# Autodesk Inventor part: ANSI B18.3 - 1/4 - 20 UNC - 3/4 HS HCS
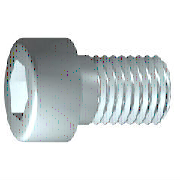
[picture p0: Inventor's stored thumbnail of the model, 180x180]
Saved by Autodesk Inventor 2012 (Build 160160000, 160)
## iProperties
IsCustomPart: 0
Created: 2011-02
Part Number: ANSI B18.3 - 1/4 - 20 UNC - 3/4 HS HCS
Material: Steel, Mild
Description: Hexagon Socket Head Cap Screw
Document SubType Name: Modeling
Standard: ANSI B18.3
Designer: Owner
Standard Revision: 2003
Standards Organization: ANSI
Language: en-US
Size Designation: 1/4 - 20 UNC - 3/4
Categories: <MemberInstance><Categories><Category DisplayName="Fasteners" InternalName="e4da775c-781d-43d5-af7c-5136215cf5a6" Mnemonic="FSTN"><Category DisplayName="Bolts"
Density: 7.86 g/cm^3
Mass: 7.66854 g
Surface Area: 7.48934 cm^2
Volume: 0.975641 cm^3
Author: Owner
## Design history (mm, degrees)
body "Solid1"
workplane "Work Plane1"
fillet "Fillet2" dims "d30" = 0.1778 (= R)
revolve "Body" stored, may be unused: angle "d10" = 90 deg
sketch "Sketch2"
  geometry: L1 (0, -6.668)-(0, 6.668) reference; L2 (-6.668, 0)-(6.668, 0) reference; L3 (2.757, 0)-(1.378, -2.388); L4 (1.378, -2.388)-(-1.378, -2.388); L5 (-1.378, -2.388)-(-2.757, 0); L6 (-2.757, 0)-(-1.378, 2.388); L7 (-1.378, 2.388)-(1.378, 2.388); L8 (1.378, 2.388)-(2.757, 0); 2 further points
  constraints: 12 end point, 1 coincident, 1 horizontal alignment, 1 point on line, 12 other
extrude "Slot" join sketch "Sketch2" stored distance "d11" = 10; taper "d12" = 0 deg
fillet "Fillet1" dims "d17" = 0.635 (= RR)
feature "Thread" dims "d13" = 15.8748 (= GEL), "d14" = 0
chamfer "Chamfer1" distance "d15" = 0.75565 (= -0.5 x SPD + 0.5 x GD); stored, may be unused: second distance "d16" = 0.75565 (= GUL), angle "d27" = 45 deg
sketch "Sketch1"
  geometry: L1 (-1.71, 0)-(19.05, 0); L2 (19.05, 0)-(19.05, 3.175); L3 (19.05, 3.175)-(3.175, 3.175); L4 (3.175, 3.175)-(0, 3.175); L5 (0, 3.175)-(0, 3.175); L6 (0, 3.175)-(0, 4.763); L7 (0, 4.763)-(-6.35, 4.763); L8 (-6.35, 4.763)-(-6.35, 2.757); L9 (-6.35, 2.757)-(-3.302, 2.757); L10 (-3.302, 2.757)-(-1.71, 0); L11 (-11.43, 0)-(24.13, 0) reference; L12 (0, -0.953)-(0, 5.715) reference; L13 (3.175, 3.175)-(0, 3.175)
  constraints: 22 end point, 6 parallel, 2 collinear, 2 perpendicular, 1 horizontal, 1 point on line
  dimensions: "d1" = 15.8748 distance from line of L3.end L2 (= GEL); "d2" = 3.1751 distance of L4.end L3.end (computed from GAL); "d3" = 6.35 distance between parallel lines of L8 L6 (= KOH); "d4" = 3.048 distance of L8.end L9.end (= INTI); "d5" = 60 deg angle of L10 L1; "d6" = 6.35 diameter of L3 L1 (= GD); "d7" = 6.35 diameter of L5 L1 (= BDM); "d8" = 5.51393 diameter of L9 L1 (= 1.1547 x SW); "d9" = 9.525 diameter of L7 L1 (= KOD); "d26" = 19.05 distance between parallel lines of L12 L2 (= NLG)
other parameters: "GD" = 6.35 [user parameter; used in 2 equation terms], "NLG" = 19.05 [user parameter; used in 1 equation term], "GEL" = 15.8748 [user parameter; used in 2 equation terms], "KOD" = 9.525 [user parameter; used in 1 equation term], "KOH" = 6.35 [user parameter; used in 1 equation term], "INTI" = 3.048 [user parameter; used in 1 equation term], "GAL" = 3.175 [user parameter; used in 1 equation term], "GUL" = 0.75565 [user parameter; used in 1 equation term], "BDM" = 6.35 [user parameter; used in 1 equation term], "SW" = 4.7752 [user parameter; used in 2 equation terms], "RR" = 0.635 [user parameter; used in 1 equation term], "SPD" = 4.8387 [user parameter; used in 2 equation terms], "d19" = 0, "d28" = 0, "d29" = 0, "R" = 0.1778 [user parameter; used in 1 equation term], "PHH" = 0.2032 [user parameter], "GD1" = 4.8387 (= SPD) [user parameter], "THREADDIA" = 6.35 [user parameter], "FAWI" = 45 deg [user parameter], "PTC" = 1.27 (computed from TPU) [user parameter], "KOH1" = 5.715 [user parameter], "NND" = 6.35 [user parameter], "TOA" = 30 deg [user parameter], "E0" = 5.51536 (= 1.155 x SW) [user parameter]
